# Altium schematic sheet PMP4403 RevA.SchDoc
size 431 x 279 mm; Date: Not shown in title block; ApprovedBy: Not shown in title block; CheckedBy: Not shown in title block; Author: Not shown in title block; CompanyName: Not shown in title block; Engineer: Jackyzhang; Organization: Not shown in title block; Address1: Not shown in title block; Address2: Not shown in title block; Address3: Not shown in title block; Address4: Not shown in title block; DocumentNumber: 1; Revision: A; SheetNumber: 1; SheetTotal: 1; PageSetup: Record=PageOptions¦CenterHorizontal=True¦CenterVertical=True¦PrintScale=1.00¦XCorrection=1.00¦YCorrection=1.00¦PrintKind=0¦BorderSize=5000000¦LeftOffset=0¦BottomOffset=0¦Orientation=2¦PaperLength=1000¦PaperWidth=1000¦Scale=100¦PaperSource=15¦PrintQuality=600¦MediaType=1¦DitherType=10¦PaperKind=Letter¦PrintScaleMode=1
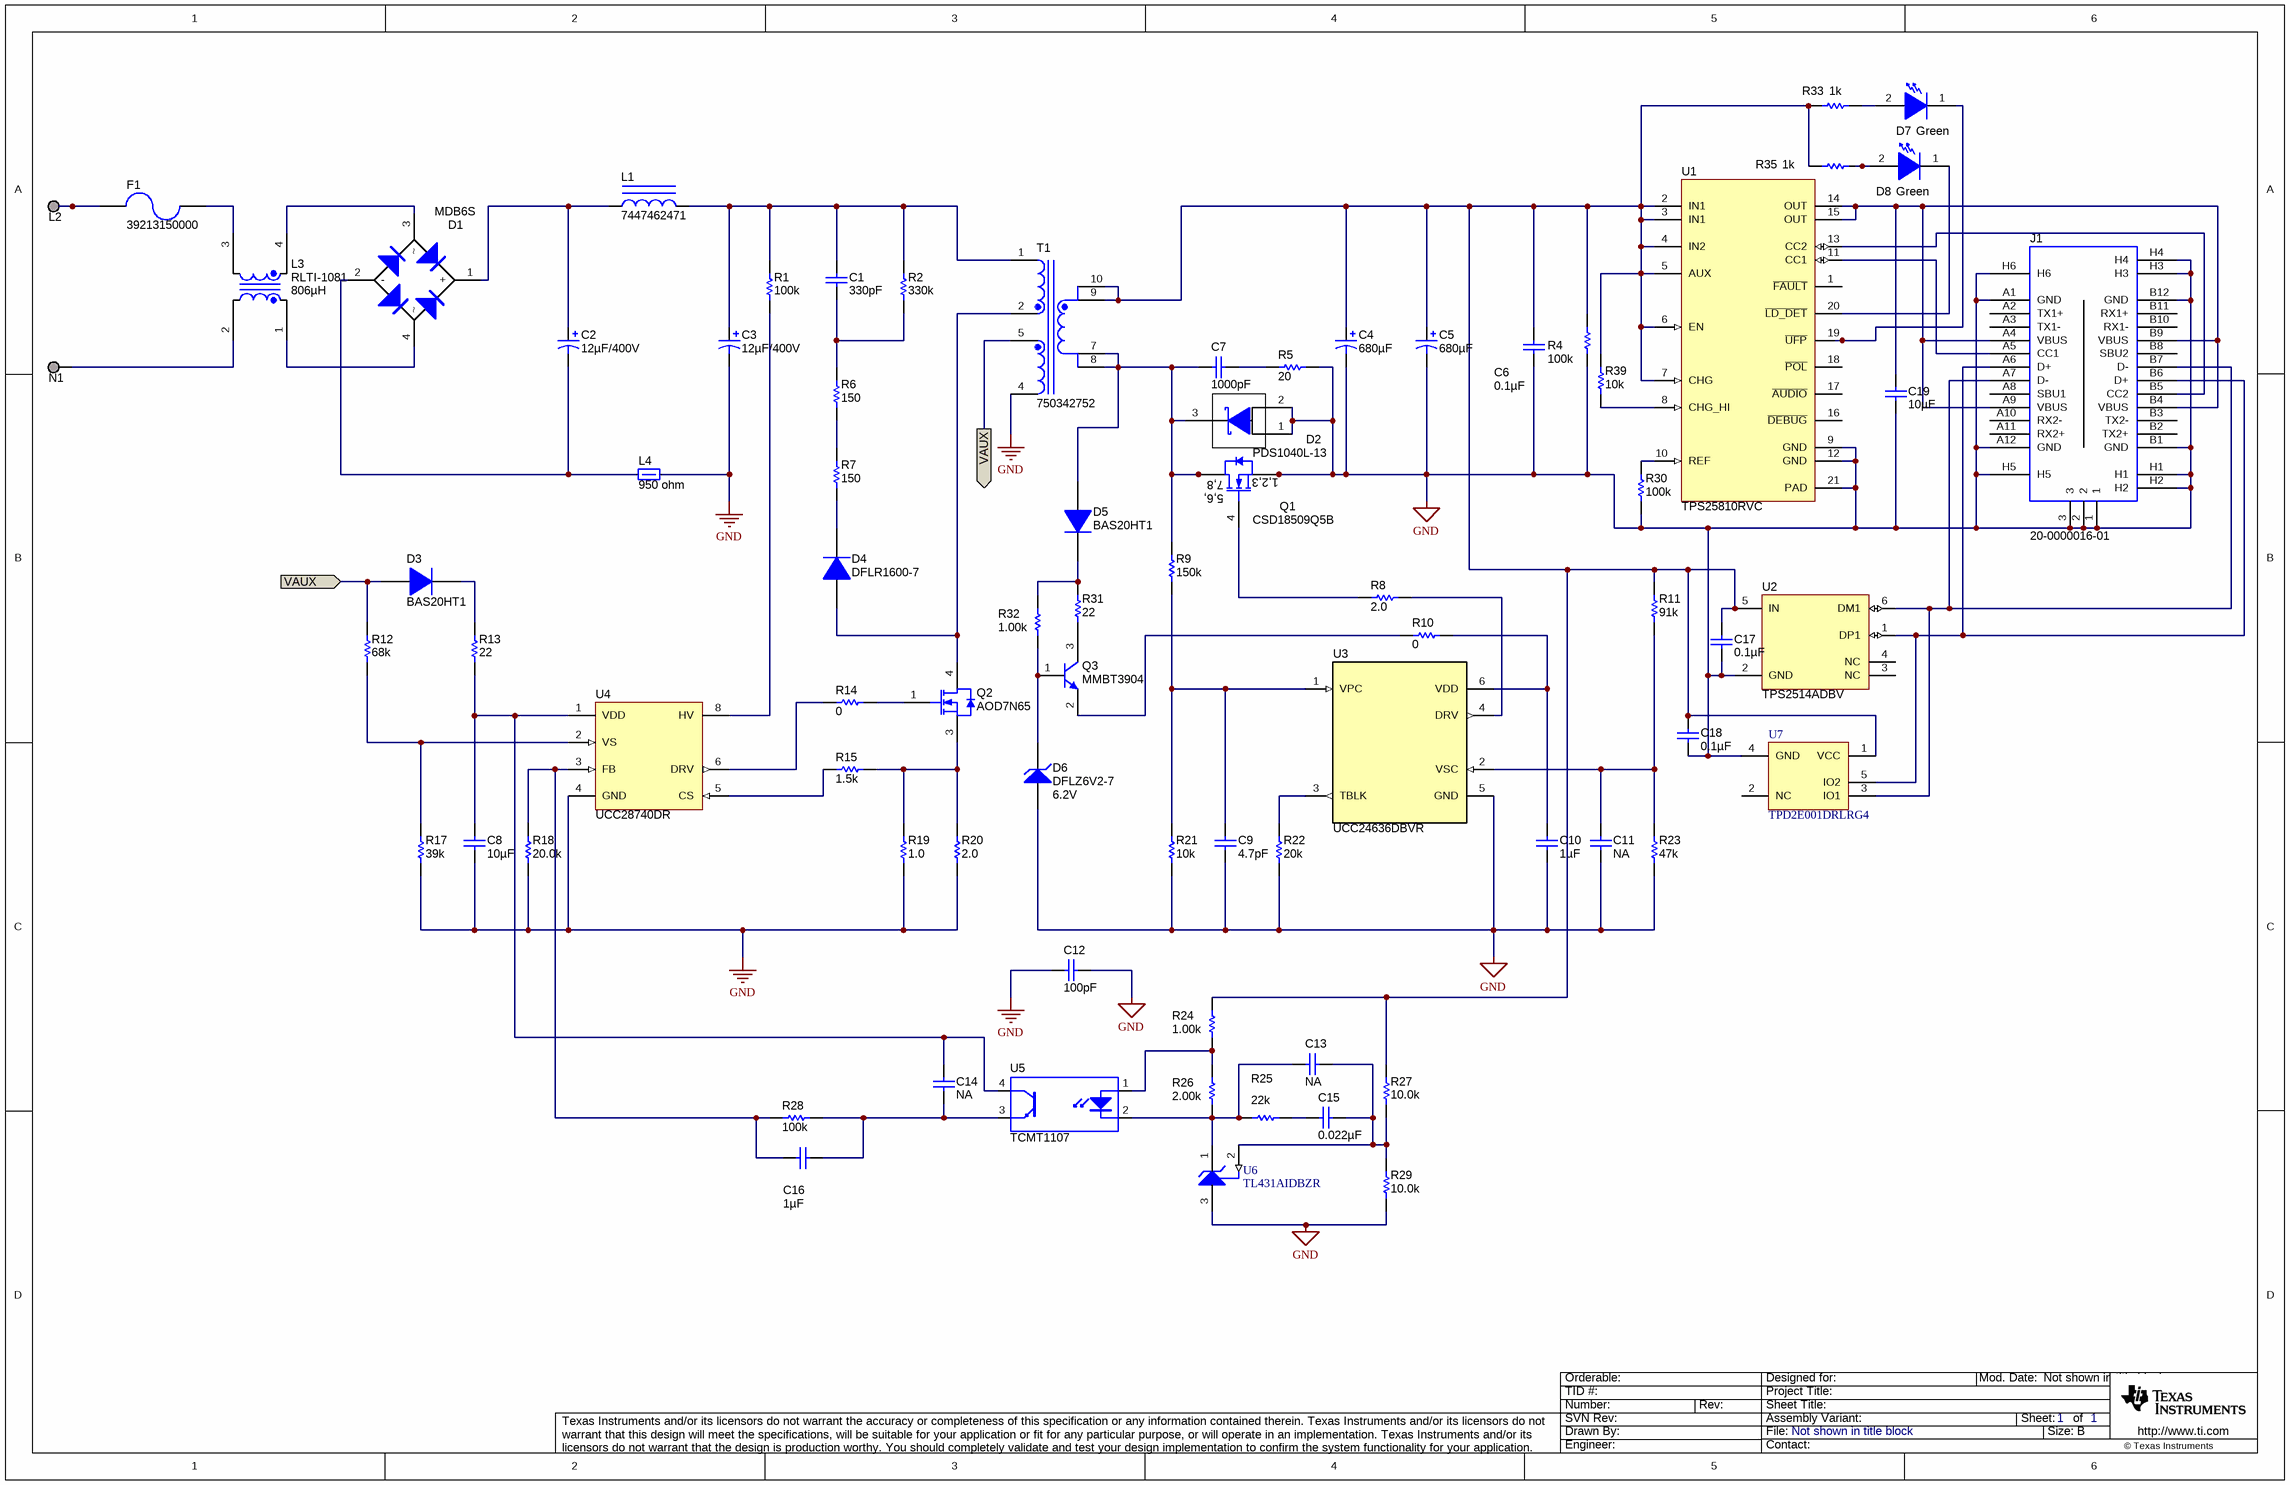
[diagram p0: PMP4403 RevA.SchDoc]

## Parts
C1  ValueDisplayed: 330pF  [1206]  (hidden comment: GRM31A5C2J331JW01D)
C2  ValueDisplayed: 12µF/400V  [CAPPR5-10X20]  (hidden comment: EEUED2G100)
C3  ValueDisplayed: 12µF/400V  [CAPPR5-10X20]  (hidden comment: EEUED2G100)
C4  ValueDisplayed: 680µF  [SEPC_C9]  (hidden comment: 6SEPC470MW)
C5  ValueDisplayed: 680µF  [SEPC_C9]  (hidden comment: 6SEPC470MW)
C6  ValueDisplayed: 0.1µF  [0603]  (hidden comment: C1608X7R1E104K)
C7  ValueDisplayed: 1000pF  [0603]  (hidden comment: 06035A102KAT2A)
C8  ValueDisplayed: 10µF  [1206_190]  (hidden comment: GMK316AB7106KL-TR)
C9  ValueDisplayed: 4.7pF  [0603]  (hidden comment: 06035A150JAT2A)
C10  ValueDisplayed: 1µF  [0603]  (hidden comment: GRM188R61E105KA12D)
C11  ValueDisplayed: NA  [0603]  (hidden comment: 06035A150JAT2A)
C12  ValueDisplayed: 100pF  [CAPRD1000W60D1000H1400]  (hidden comment: DE1B3KX101K)
C13  ValueDisplayed: NA  [0603]  (hidden comment: C0603X223K5RACTU)
C14  ValueDisplayed: NA  [0603]  (hidden comment: C0603X223K5RACTU)
C15  ValueDisplayed: 0.022µF  [0603]  (hidden comment: C0603X223K5RACTU)
C16  ValueDisplayed: 1µF  [0603_095]  (hidden comment: C0603C105K3RACTU)
C17  ValueDisplayed: 0.1µF  [0603]  (hidden comment: 06033C104JAT2A)
C18  ValueDisplayed: 0.1µF  [0603]  (hidden comment: 06033C104JAT2A)
C19  ValueDisplayed: 10µF  [0805_HV]  (hidden comment: C0805C106K8PACTU)
D1  MDB6S  [MICRODIP_4]
D2  PDS1040L-13  [PowerDI5]
D3  BAS20HT1  [sod-323]
D4  DFLR1600-7  [powerDI123]
D5  BAS20HT1  [sod-323]
D6  DFLZ6V2-7  value 6.2V  [powerDI123]
D7  value Green  [WL-SMCW_GREEN]  (hidden comment: 150060GS75000)
D8  value Green  [WL-SMCW_GREEN]  (hidden comment: 150060GS75000)
F1  39213150000  [FUSE_392]
J1  20-0000016-01  [Lintes_20-0000016-01]
L1  7447462471  [WE-TI_5075]
L2  TESTPOINT  [Keystone_5019]  (value not drawn)  (no BOM)
L3  RLTI-1081  ValueDisplayed: 806µH  [IND_RLTI-1081]
L4  value 950 ohm  [1206]  (hidden comment: HZ1206E152R-10)
N1  TESTPOINT  [Keystone_5019]  (value not drawn)  (no BOM)
Q1  CSD18509Q5B  [TRANS_NexFET_Q5B]
Q2  AOD7N65  [DPAK]
Q3  MMBT3904  [SOT-23]
R1  ValueDisplayed: 100k  [1206]  (hidden comment: CRCW1206100KJNEA)
R2  ValueDisplayed: 330k  [1206]  (hidden comment: CRCW1206330KJNEA)
R4  ValueDisplayed: 100k  [0603]  (hidden comment: CRCW0603100KJNEA)
R5  ValueDisplayed: 20  [0805_HV]  (hidden comment: CRCW080520R0JNEA)
R6  ValueDisplayed: 150  [1206]  (hidden comment: CRCW1206150RJNEA)
R7  ValueDisplayed: 150  [1206]  (hidden comment: CRCW1206150RJNEA)
R8  ValueDisplayed: 2.0  [0603]  (hidden comment: CRCW06032R00JNEA)
R9  ValueDisplayed: 150k  [0603]  (hidden comment: CRCW0603150KFKEA)
R10  ValueDisplayed: 0  [0603]  (hidden comment: CRCW06032R00JNEA)
R11  ValueDisplayed: 91k  [0603]  (hidden comment: CRCW060391K0JNEA)
R12  ValueDisplayed: 68k  [0603]  (hidden comment: CRCW060368K0JNEA)
R13  ValueDisplayed: 22  [0603]  (hidden comment: CRCW060322R0JNEA)
R14  ValueDisplayed: 0  [0603]  (hidden comment: CRCW06030000Z0EA)
R15  ValueDisplayed: 1.5k  [0603]  (hidden comment: CRCW06031K50JNEA)
R17  ValueDisplayed: 39k  [0603]  (hidden comment: CRCW060339K0JNEA)
R18  ValueDisplayed: 20.0k  [0603]  (hidden comment: CRCW060320K0FKEA)
R19  ValueDisplayed: 1.0  [1206]  (hidden comment: CRCW12061R00JNEA)
R20  ValueDisplayed: 2.0  [1206]  (hidden comment: CRCW12062R00JNEA)
R21  ValueDisplayed: 10k  [0603]  (hidden comment: CRCW060310K0JNEA)
R22  ValueDisplayed: 20k  [0603]  (hidden comment: CRCW060313K0JNEA)
R23  ValueDisplayed: 47k  [0603]  (hidden comment: CRCW060347K0JNEA)
R24  ValueDisplayed: 1.00k  [0603]  (hidden comment: CRCW06031K00FKEA)
R25  ValueDisplayed: 22k  [0603]  (hidden comment: CRCW060322K0JNEA)
R26  ValueDisplayed: 2.00k  [0603]  (hidden comment: CRCW06032K00FKEA)
R27  ValueDisplayed: 10.0k  [0603]  (hidden comment: CRCW060310K0FKEA)
R28  ValueDisplayed: 100k  [0603]  (hidden comment: CRCW0603100KFKEA)
R29  ValueDisplayed: 10.0k  [0603]  (hidden comment: CRCW060310K0FKEA)
R30  ValueDisplayed: 100k  [0603]  (hidden comment: CRCW0603100KFKEA)
R31  ValueDisplayed: 22  [0805_HV]  (hidden comment: CRCW080522R0JNEA)
R32  ValueDisplayed: 1.00k  [0603]  (hidden comment: CRCW06031K00FKEA)
R33  ValueDisplayed: 1k  [0603]  (hidden comment: CRCW060310K0JNEA)
R35  ValueDisplayed: 1k  [0603]  (hidden comment: CRCW060310K0JNEA)
R39  ValueDisplayed: 10k  [0603]  (hidden comment: CRCW060310K0JNEA)
T1  750342752  [Wurth_750342752]
U1  TPS25810RVC  [RVC0020A]
U2  TPS2514ADBV  [DBV0006A_N]
U3  UCC24636DBVR  [DBV0006A_N]
U4  UCC28740DR  [D0007A_N]
U5  TCMT1107  [SOP-4]
U6  TL431AIDBZR  [DBZ0003A_N]
U7  TPD2E001DRLRG4  [DRL0005A]

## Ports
VAUX (in), VAUX (out)

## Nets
GND: C3.2(-) C4.2(-) C5.2(-) C6.2 C8.2 C9.2 C10.2 C11.2 C12.1 C12.2 C17.2 C18.2 C19.2 D2.1(A) D2.2(A) D6.2(A) J1.1 J1.2 J1.3 J1.A1(GND) J1.A12(GND) J1.B1(GND) J1.B12(GND) J1.H1 J1.H2 J1.H3 J1.H4 J1.H5 J1.H6 L4.2 Q1.1(S) Q1.2(S) Q1.3(S) R4.1 R5.2 R17.1 R18.1 R19.1 R20.1 R21.1 R22.1 R23.1 R29.1 R30.1 T1.4 U1.9(GND) U1.12(GND) U1.21(PAD) U2.2(GND) U3.5(GND) U4.4(GND) U6.3(ANODE) U7.4(GND)
VAUX: D3.2(A) R12.2 T1.5 ; port VAUX
NetC1_1: C1.1 C3.1(+) L1.2 R1.2 R2.2 T1.1
NetC1_2: C1.2 R2.1 R6.2
NetC2_1: C2.1(+) D1.1(+) L1.1
NetC2_2: C2.2(-) D1.2(-) L4.1
NetC4_1: C4.1(+) C5.1(+) C6.1 C17.1 C18.1 R4.2 R11.2 R24.2 R27.2 R33.2 R35.2 R39.2 T1.9 T1.10 U1.2(IN1) U1.3(IN1) U1.4(IN2) U1.5(AUX) U1.6(EN) U1.7(CHG) U2.5(IN) U7.1(VCC)
NetC7_1: C7.1 R5.1
NetC7_2: C7.2 D2.3(K) D5.2(A) Q1.5(D) Q1.6(D) Q1.7(D) Q1.8(D) R9.2 T1.7 T1.8
NetC8_1: C8.1 C14.1 R13.1 U4.1(VDD) U5.4(C)
NetC9_1: C9.1 R9.1 R21.2 U3.1(VPC)
NetC10_1: C10.1 R10.1 U3.6(VDD)
NetC11_1: C11.1 R11.1 R23.2 U3.2(VSC)
NetC13_1: C13.1 C15.1 R27.1 R29.2 U6.2(REF)
NetC13_2: C13.2 R25.1 R26.1 U5.2(K) U6.1(CATHODE)
NetC14_2: C14.2 C16.1 R28.2 U5.3(E)
NetC15_2: C15.2 R25.2
NetC16_2: C16.2 R18.2 R28.1 U4.3(FB)
NetC19_1: C19.1 J1.A4(VBUS) J1.A9(VBUS) J1.B4(VBUS) J1.B9(VBUS) U1.14(OUT) U1.15(OUT)
NetD1_3: D1.3 L3.4
NetD1_4: D1.4 L3.1
NetD3_1: D3.1(K) R13.2
NetD4_1: D4.1(K) R7.1
NetD4_2: D4.2(A) Q2.4(D) T1.2
NetD5_1: D5.1(K) R31.2 R32.2
NetD6_1: D6.1(K) Q3.1(B) R32.1
NetD7_1: D7.1(K) U1.19(~{UFP})
NetD7_2: D7.2(A) R33.1
NetD8_1: D8.1(K) U1.20(~{LD_DET})
NetD8_2: D8.2(A) R35.1
NetF1_1: F1.1 L3.3
NetF1_2: F1.2 L2.1
NetJ1_A5: J1.A5(CC1) U1.11(CC1)
NetJ1_A6: J1.A6(D+) J1.B6(D+) U2.1(DP1) U7.5(IO2)
NetJ1_A7: J1.A7(D-) J1.B7(D-) U2.6(DM1) U7.3(IO1)
NetJ1_B5: J1.B5(CC2) U1.13(CC2)
NetL3_2: L3.2 N1.1
NetQ1_4: Q1.4(G) R8.1
NetQ2_1: Q2.1(G) R14.2
NetQ2_3: Q2.3(S) R15.2 R19.2 R20.2
NetQ3_2: Q3.2(E) R10.2
NetQ3_3: Q3.3(C) R31.1
NetR1_1: R1.1 U4.8(HV)
NetR6_1: R6.1 R7.2
NetR8_2: R8.2 U3.4(DRV)
NetR12_1: R12.1 R17.2 U4.2(VS)
NetR14_1: R14.1 U4.6(DRV)
NetR15_1: R15.1 U4.5(CS)
NetR22_2: R22.2 U3.3(TBLK)
NetR24_1: R24.1 R26.2 U5.1(A)
NetR30_2: R30.2 U1.10(REF)
NetR39_1: R39.1 U1.8(CHG_HI)

Not connected (* = marked no-connect by the designer): J1 A2(TX1+) A3(TX1-) A8(SBU1) A10(RX2-) A11(RX2+) B2(TX2+) B3(TX2-) B8(SBU2) B10(RX1-) B11(RX1+); U1 1(~{FAULT}) 16(~{DEBUG}) 17(~{AUDIO}) 18(~{POL}); U2 3(NC) 4(NC); U7 2(NC)

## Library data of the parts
C1 = GRM31A5C2J331JW01D: CAP, CERM, 330 pF, 630 V, +/- 5%, C0G/NP0, 1206; Manufacturer: MuRata; Polarized: N; CompType: Capacitor; Value: 330pF; U/M: EA; Cap_F: 0.00000000033; Tolerance_%: 5; Value1: Unknown; VDC_V: 630; Value2: 630V; TaMin_C: -55; TaMax_C: 125
C2 C3 = EEUED2G100: CAP, AL, 10 µF, 400 V, +/- 20%, 2.864788 ohm, TH; Manufacturer: Panasonic; Polarized: Y; CompType: Capacitor; Value: 12uF; U/M: EA; Cap_F: 0.00001; Tolerance_%: 20; VDC_V: 400; Value2: 400V; IRMS_A: 0.3; TaMin_C: -25; TaMax_C: 105
C4 C5 = 6SEPC470MW: CAP, AL, 470 µF, 6.3 V, +/- 20%, 0.007 ohm, TH; Manufacturer: Panasonic; Polarized: Y; CompType: Capacitor; Value: 470uF; U/M: EA; Cap_F: 0.00047; Tolerance_%: 20; VDC_V: 6.3; Value2: 6.3V; ESR_ohm: 0.007; IRMS_A: 5.6; TaMin_C: -55; TaMax_C: 105; Cap_Case: 6.3x9
C6 = C1608X7R1E104K: CAP, CERM, 0.1 µF, 25 V, +/- 10%, X7R, 0603; Manufacturer: TDK; Polarized: N; CompType: Capacitor; Value: 0.1uF; U/M: EA; Cap_F: 0.0000001; Tolerance_%: 10; ESR_ohm: 0.017; Value1: 0.017 ohm; VDC_V: 25; Value2: 25V; TaMin_C: -55; TaMax_C: 125
C7 = 06035A102KAT2A: CAP, CERM, 1000 pF, 50 V, +/- 10%, C0G/NP0, 0603; Manufacturer: AVX; Polarized: N; CompType: Capacitor; Value: 1000pF; U/M: EA; Cap_F: 0.000000001; Tolerance_%: 10; ESR_ohm: 0.048; Value1: 0.048 ohm; VDC_V: 50; Value2: 50V; TaMin_C: -55; TaMax_C: 125
C8 = GMK316AB7106KL-TR: CAP, CERM, 10 µF, 35 V, +/- 10%, X7R, 1206_190; Manufacturer: Taiyo Yuden; Polarized: N; CompType: Capacitor; Value: 10uF; U/M: EA; Cap_F: 0.00001; Tolerance_%: 10; Value1: Unknown; VDC_V: 35; Value2: 35V; TaMin_C: -55; TaMax_C: 125; Cap_Case: 1206
C9 C11 = 06035A150JAT2A: CAP, CERM, 15 pF, 50 V, +/- 5%, C0G/NP0, 0603; Manufacturer: AVX; Polarized: N; CompType: Capacitor; Value: 15pF; U/M: EA; Cap_F: 0.000000000015; Tolerance_%: 5; ESR_ohm: 0.32; Value1: 0.32 ohm; VDC_V: 50; Value2: 50V; TaMin_C: -55; TaMax_C: 125
C10 = GRM188R61E105KA12D: CAP, CERM, 1 µF, 25 V, +/- 10%, X5R, 0603; Manufacturer: MuRata; Polarized: N; CompType: Capacitor; Value: 1uF; U/M: EA; Cap_F: 0.000001; Tolerance_%: 10; Value1: Unknown; VDC_V: 25; Value2: 25V; TaMin_C: -55; TaMax_C: 85
C12 = DE1E3KX222MA5BA01: CAP, CERM, 100 pF, 250 V, +/- 20%, E, Disc 10x8mm; Manufacturer: MuRata; Polarized: N; CompType: Capacitor; Value: 100pF; U/M: EA; Cap_F: 0.0000000022; Tolerance_%: 20; Value1: Unknown; VDC_V: 250; Value2: 250V; TaMin_C: -25; TaMax_C: 85
C13-C15 = C0603X223K5RACTU: CAP, CERM, 0.022 µF, 50 V, +/- 10%, X7R, 0603; Manufacturer: Kemet; Polarized: N; CompType: Capacitor; Value: 0.022uF; U/M: EA; Cap_F: 0.000000022; Tolerance_%: 10; Value1: Unknown; VDC_V: 50; Value2: 50V; TaMin_C: -55; TaMax_C: 125
C16 = C0603C105K3RACTU: CAP, CERM, 1 µF, 25 V, +/- 10%, X7R, 0603_095; Manufacturer: Kemet; Polarized: N; CompType: Capacitor; Value: 1uF; U/M: EA; Cap_F: 0.000001; Tolerance_%: 10; Value1: Unknown; VDC_V: 25; Value2: 25V; TaMin_C: -55; TaMax_C: 125; Cap_Case: 0603
C17 C18 = 06033C104JAT2A: CAP, CERM, 0.1 µF, 25 V, +/- 5%, X7R, 0603; Manufacturer: AVX; Polarized: N; CompType: Capacitor; Value: 0.1uF; U/M: EA; Cap_F: 0.0000001; Tolerance_%: 5; ESR_ohm: 0.05; Value1: 0.05 ohm; VDC_V: 25; Value2: 25V; TaMin_C: -55; TaMax_C: 125
C19 = C0805C106K8PACTU: CAP, CERM, 10 µF, 10 V, +/- 10%, X5R, 0805; Manufacturer: Kemet; Polarized: N; CompType: Capacitor; Value: 10uF; U/M: EA; Cap_F: 0.00001; Tolerance_%: 10; ESR_ohm: 0.003; Value1: 0.003 ohm; Value2: 10V; IRMS_A: 11.43; TaMin_C: -55; TaMax_C: 85; Cap_Case: 0805
D1 = MDB6S: Diode, Switching-Bridge, 600 V, 1 A, Diode Bridge,6.5x1.3x5.0mm, SMT; Manufacturer: Fairchild Semiconductor; U/M: EA; Vf_V: 1.1; Value: 600V; Value1: 1A; Value2: 1.1V; Io_A: 1; Vr_V: 600; TJmax_C: 150
D2 = PDS1040L-13: Diode, Schottky, 40 V, 10 A, PowerDI5; Manufacturer: Diodes Inc.; U/M: EA; Vf_V: 0.49; Value: 40V; Value1: 10A; Value2: 0.49V; Io_A: 10; Vr_V: 40; TJmax_C: 150; RJC_CperW: 85
D3 D5 = BAV20WS-TP: Diode, P-N, 150 V, 0.2 A, SOD-323; Manufacturer: ON Semiconductor; U/M: EA; Vf_V: 1.25; Value: 150V; Value1: 0.2A; Value2: 1.25V; Io_A: 0.2; Vr_V: 150
D4 = DFLR1600-7: Diode, Standard Recovery Rectifier, 600 V, 1 A, PowerDI123; Manufacturer: Diodes Inc.; U/M: EA; Vf_V: 1.1; Value: 600V; Value1: 1A; Value2: 1.1V; Io_A: 1; Vr_V: 600; TJmax_C: 150
D6 = DFLZ6V2-7: Diode, Zener, 6.2 V, 1 W, PowerDI123; Manufacturer: Diodes Inc.; SymbolCreator: a0412235; U/M: EA; Power_W: 1; Vz_V: 6.2; Value1: 1W; RJA_CperW: 110
D7 D8 = 150060GS75000: LED, Green, SMD; Manufacturer: Wurth Elektronik; Type: InGaN; Vf_V: 3.2; Value2: 3.2V; Io_A: 0.02; Tjmax_C: 85; Value1: W; Angle: 140; U/M: EA
F1 = 39213150000: Fuse, 3.15 A, 250 V, TH; Manufacturer: Littelfuse; U/M: EA; OpeningTime_200%_max: 120; VDC_V: 250; Irating_A: 3.15; Vdrop: 0.08; Soldering_Wave_MaxTemp_C: 260; Soldering_Wave_MaxTime_s: 5
J1 = 20-0000016-01: Connector, Receptacle, USB Type C, R/A, SMT; Manufacturer: Lintes Technology; SymbolCreator: Altium; U/M: EA
L1 = 7447462471: Inductor, Unshielded Drum Core, Ferrite, 470 µH, 0.35 A, 1.58 ohm, TH; Manufacturer: Wurth Elektronik; Value: 470uH; Ind_H: 470.0E-6; ValueDisplayed: 470µH; Imax_A: 0.35; Irms: 0.35A @ 40C rise; Isat: 0.4A @ 10% inductance drop; DCR_ohm: 1.58; Value2: 0.35A
L2 N1 = 5019: Test Point, Miniature, SMT; Manufacturer: Keystone; CompType: Test Point Loop; U/M: EA
L3 = RLTI-1081: Coupled inductor, 806 µH,  A, 0.27 ohm, +/- 25%, TH; Manufacturer: Renco Electronics; SymbolCreator: a0412235; Ind_H: 806.0E-6; DCR_ohm: 0.27; Tolerance_%: 25; Value: 806uH
L4 = HZ1206E152R-10: Ferrite Bead, 950 ohm @ 100 MHz, 0.5 A, 1206; Manufacturer: Laird-Signal Integrity Products; Imax_A: 0.5; DCR_ohm: 0.3; Value1: 0.3 ohm; Value2: 0.5A; ZTyp@100MHz_Ohm: 950; Ztyp@1GHz_Ohm: 57
Q1 = CSD18509Q5B: MOSFET, N-CH, 40 V, 38 A, SON 5x6mm; Manufacturer: Texas Instruments; Alternate Manufacturer: None; U/M: EA; ChType: N; Value: 40V; VdsMax_V: 40; Value1: 0.0017 ohm; Rdson45_ohm: 0.0017; Value2: 150 nC; QgTyp_nC: 150; Vgs_V: 20; IdsMax_A: 38
Q2 = AOD7N65: MOSFET, N-CH, 650 V, 7 A, DPAK; Manufacturer: AOS; Alternate Manufacturer: None; U/M: EA; ChType: N; Value: 650V; VdsMax_V: 650; Value1: ? ohm; Value2: 19.6 nC; QgTyp_nC: 19.6; Vgs_V: 30; IdsMax_A: 7
Q3 = MMBT3904, Fairchild Semiconductor: Transistor, NPN, 40 V, 0.2 A, SOT-23; CompType: BJT; PNP: 0; NPN: 1; Vceo_V: 40; Vcesat1_V: 0.2; Value: 40 V; Value1: 0.2 A; HfeMax: 300; TaMin_C: -55; TaMax_C: 150; U/M: EA
R1 = CRCW1206100KJNEA: RES, 100 k, 5%, 0.25 W, 1206; Manufacturer: Vishay-Dale; CompType: Resistor; Value: 100k; Res_ohm: 100000; Tolerance_%: 5; Power_W: 0.25; Value2: 0.25W; VDC_V: 200; TempCo: 200 ppm/C; EIA_Code: E24; U/M: EA
R2 = CRCW1206330KJNEA: RES, 330 k, 5%, 0.25 W, 1206; Manufacturer: Vishay-Dale; CompType: Resistor; Value: 330k; Res_ohm: 330000; Tolerance_%: 5; Power_W: 0.25; Value2: 0.25W; VDC_V: 200; TempCo: 200 ppm/C; EIA_Code: E24; U/M: EA
R4 = CRCW0603100KJNEA: RES, 100 k, 5%, 0.1 W, 0603; Manufacturer: Vishay-Dale; CompType: Resistor; Value: 100k; Res_ohm: 100000; Tolerance_%: 5; Power_W: 0.1; Value2: 0.1W; VDC_V: 75; TempCo: 200 ppm/C; EIA_Code: E24; U/M: EA
R5 = CRCW080520R0JNEA: RES, 20, 5%, 0.125 W, 0805; Manufacturer: Vishay-Dale; CompType: Resistor; Value: 20; Value_Code: 20R0; Tolerance_%: 5; Power_W: 0.125; Value2: 0.125W; VDC_V: 150; TempCo: 200 ppm/C; EIA_Code: E24; U/M: EA
R6 R7 = CRCW1206150RJNEA: RES, 150, 5%, 0.25 W, 1206; Manufacturer: Vishay-Dale; CompType: Resistor; Value: 150; Value_Code: 150R; Tolerance_%: 5; Power_W: 0.25; Value2: 0.25W; VDC_V: 200; TempCo: 200 ppm/C; EIA_Code: E24; U/M: EA
R8 R10 = CRCW06032R00JNEA: RES, 2.0, 5%, 0.1 W, 0603; Manufacturer: Vishay-Dale; CompType: Resistor; Value: 2.0; Res_ohm: 2; Value_Code: 2R00; Tolerance_%: 5; Power_W: 0.1; Value2: 0.1W; VDC_V: 75; TempCo: 200 ppm/C; EIA_Code: E24; U/M: EA
R9 = CRCW0603150KFKEA: RES, 150 k, 1%, 0.1 W, 0603; Manufacturer: Vishay-Dale; CompType: Resistor; Value: 150k; Res_ohm: 150000; Tolerance_%: 1; Power_W: 0.1; Value2: 0.1W; VDC_V: 75; TempCo: 100 ppm/C; EIA_Code: E96; U/M: EA
R11 = CRCW060391K0JNEA: RES, 91 k, 5%, 0.1 W, 0603; Manufacturer: Vishay-Dale; CompType: Resistor; Value: 91k; Res_ohm: 91000; Value_Code: 91k0; Tolerance_%: 5; Power_W: 0.1; Value2: 0.1W; VDC_V: 75; TempCo: 200 ppm/C; EIA_Code: E24; U/M: EA
R12 = CRCW060368K0JNEA: RES, 68 k, 5%, 0.1 W, 0603; Manufacturer: Vishay-Dale; CompType: Resistor; Value: 68k; Res_ohm: 68000; Value_Code: 68k0; Tolerance_%: 5; Power_W: 0.1; Value2: 0.1W; VDC_V: 75; TempCo: 200 ppm/C; EIA_Code: E24; U/M: EA
R13 = CRCW060322R0JNEA: RES, 22, 5%, 0.1 W, 0603; Manufacturer: Vishay-Dale; CompType: Resistor; Value: 22; Value_Code: 22R0; Tolerance_%: 5; Power_W: 0.1; Value2: 0.1W; VDC_V: 75; TempCo: 200 ppm/C; EIA_Code: E24; U/M: EA
R14 = CRCW06030000Z0EA: RES, 0, 5%, 0.1 W, 0603; Manufacturer: Vishay-Dale; CompType: Resistor; Value: 0; Value_Code: 0000; Tolerance_%: 5; Power_W: 0.1; Value2: 0.1W; VDC_V: 75; TempCo: 200 ppm/C; EIA_Code: E24; U/M: EA
R15 = CRCW06031K50JNEA: RES, 1.5 k, 5%, 0.1 W, 0603; Manufacturer: Vishay-Dale; CompType: Resistor; Value: 1.5k; Res_ohm: 1500; Value_Code: 1k50; Tolerance_%: 5; Power_W: 0.1; Value2: 0.1W; VDC_V: 75; TempCo: 200 ppm/C; EIA_Code: E24; U/M: EA
R17 = CRCW060339K0JNEA: RES, 39 k, 5%, 0.1 W, 0603; Manufacturer: Vishay-Dale; CompType: Resistor; Value: 39k; Res_ohm: 39000; Value_Code: 39k0; Tolerance_%: 5; Power_W: 0.1; Value2: 0.1W; VDC_V: 75; TempCo: 200 ppm/C; EIA_Code: E24; U/M: EA
R18 = CRCW060320K0FKEA: RES, 20.0 k, 1%, 0.1 W, 0603; Manufacturer: Vishay-Dale; CompType: Resistor; Value: 20.0k; Res_ohm: 20000; Value_Code: 20k0; Tolerance_%: 1; Power_W: 0.1; Value2: 0.1W; VDC_V: 75; TempCo: 100 ppm/C; EIA_Code: E96; U/M: EA
R19 = CRCW12061R00JNEA: RES, 1.0, 5%, 0.25 W, 1206; Manufacturer: Vishay-Dale; CompType: Resistor; Value: 1.0; Res_ohm: 1; Value_Code: 1R00; Tolerance_%: 5; Power_W: 0.25; Value2: 0.25W; VDC_V: 200; TempCo: 200 ppm/C; EIA_Code: E24; U/M: EA
R20 = CRCW12062R00JNEA: RES, 2.0, 5%, 0.25 W, 1206; Manufacturer: Vishay-Dale; CompType: Resistor; Value: 2.0; Res_ohm: 2; Value_Code: 2R00; Tolerance_%: 5; Power_W: 0.25; Value2: 0.25W; VDC_V: 200; TempCo: 200 ppm/C; EIA_Code: E24; U/M: EA
R21 R33 R35 R39 = CRCW060310K0JNEA: RES, 10 k, 5%, 0.1 W, 0603; Manufacturer: Vishay-Dale; CompType: Resistor; Value: 10k; Res_ohm: 10000; Value_Code: 10k0; Tolerance_%: 5; Power_W: 0.1; Value2: 0.1W; VDC_V: 75; TempCo: 200 ppm/C; EIA_Code: E24; U/M: EA
R22 = CRCW060313K0JNEA: RES, 13 k, 5%, 0.1 W, 0603; Manufacturer: Vishay-Dale; CompType: Resistor; Value: 13k; Res_ohm: 13000; Value_Code: 13k0; Tolerance_%: 5; Power_W: 0.1; Value2: 0.1W; VDC_V: 75; TempCo: 200 ppm/C; EIA_Code: E24; U/M: EA
R23 = CRCW060347K0JNEA: RES, 47 k, 5%, 0.1 W, 0603; Manufacturer: Vishay-Dale; CompType: Resistor; Value: 47k; Res_ohm: 47000; Value_Code: 47k0; Tolerance_%: 5; Power_W: 0.1; Value2: 0.1W; VDC_V: 75; TempCo: 200 ppm/C; EIA_Code: E24; U/M: EA
R24 R32 = CRCW06031K00FKEA: RES, 1.00 k, 1%, 0.1 W, 0603; Manufacturer: Vishay-Dale; CompType: Resistor; Value: 1.00k; Res_ohm: 1000; Value_Code: 1k00; Tolerance_%: 1; Power_W: 0.1; Value2: 0.1W; VDC_V: 75; TempCo: 100 ppm/C; EIA_Code: E96; U/M: EA
R25 = CRCW060322K0JNEA: RES, 22 k, 5%, 0.1 W, 0603; Manufacturer: Vishay-Dale; CompType: Resistor; Value: 22k; Res_ohm: 22000; Value_Code: 22k0; Tolerance_%: 5; Power_W: 0.1; Value2: 0.1W; VDC_V: 75; TempCo: 200 ppm/C; EIA_Code: E24; U/M: EA
R26 = CRCW06032K00FKEA: RES, 2.00 k, 1%, 0.1 W, 0603; Manufacturer: Vishay-Dale; CompType: Resistor; Value: 2.00k; Res_ohm: 2000; Value_Code: 2k00; Tolerance_%: 1; Power_W: 0.1; Value2: 0.1W; VDC_V: 75; TempCo: 100 ppm/C; EIA_Code: E96; U/M: EA
R27 R29 = CRCW060310K0FKEA: RES, 10.0 k, 1%, 0.1 W, 0603; Manufacturer: Vishay-Dale; CompType: Resistor; Value: 10.0k; Res_ohm: 10000; Value_Code: 10k0; Tolerance_%: 1; Power_W: 0.1; Value2: 0.1W; VDC_V: 75; TempCo: 100 ppm/C; EIA_Code: E96; U/M: EA
R28 R30 = CRCW0603100KFKEA: RES, 100 k, 1%, 0.1 W, 0603; Manufacturer: Vishay-Dale; CompType: Resistor; Value: 100k; Res_ohm: 100000; Tolerance_%: 1; Power_W: 0.1; Value2: 0.1W; VDC_V: 75; TempCo: 100 ppm/C; EIA_Code: E96; U/M: EA
R31 = CRCW080522R0JNEA: RES, 22, 5%, 0.125 W, 0805; Manufacturer: Vishay-Dale; CompType: Resistor; Value: 22; Value_Code: 22R0; Tolerance_%: 5; Power_W: 0.125; Value2: 0.125W; VDC_V: 150; TempCo: 200 ppm/C; EIA_Code: E24; U/M: EA
T1 = 750342752: Transformer, 515 uH, TH; Manufacturer: Wurth Elektronik; SymbolCreator: Altium; DCR_Ohm: 0.66; Value: 515 uH; LeakageL: 20 uH; U/M: EA
U1 = TPS25810RVC: USB Type-C DFP Controller and Power Switch with Load Detection, RVC0020A; Manufacturer: Texas Instruments; SymbolCreator: Altium; CompType: IC; U/M: EA
U2 = TPS2514ADBV: USB Dedicated Charging Port Controller, DBV0006A; Manufacturer: Texas Instruments; SymbolCreator: a0411947; CompType: IC; U/M: EA
U3 = UCC24636DBVR: SYNCRONOUS RECTIFIER CONTROLLER WITH LOW POWER STANDBY, DBV0006A; Alternate PartNumber: UCC24636DBVT; Manufacturer: Texas Instruments; SymbolCreator: a0411947; CompType: IC; U/M: EA
U4 = UCC28740DR: Constant-Voltage, Constant-Current Flyback Controller Using Opto-Coupler Feedback, D0007A; Manufacturer: Texas Instruments; SymbolCreator: a0412235; CompType: IC; U/M: EA
U5 = TCMT1107: Optocoupler, 3.75 kV, 80-160% CTR, SMD-4; Manufacturer: Vishay-Semiconductor; CTR_Min: 80% @ 5mA; CTR_Max: 160% @ 5mA; Voltage_Isolation_Vrms: 3750; tr_typ: 4us; tf_typ: 4.7us; U/M: EA
U6 = TL431AIDBZR: Adjustable Precision Shunt Regulator, 34 ppm / degC, 100 mA, -40 to 85 degC, 3-pin SOT-23 (DBZ), Green (RoHS & no Sb/Br); Manufacturer: Texas Instruments; Alternate Manufacturer: None; Alternate PartNumber: Equivalent; Initial Accuracy @ 25/deg C(%): 1; Iout/Iz(Max)(mA): 100; Min Iz for Regulation(uA): 600; Rating: Catalog; SubFamily: Shunt Voltage Reference; Temp Coeff(Max)(ppm/ degree C): 92; Temp Coeff(Typ)(ppm/ degree C): 34; VO Adj(Max)(V): 36; VO Adj(Min)(V): 2.495
U7 = TPD2E001DRLRG4: Low-Capacitance + / - 15 kV ESD-Protection Array for High-Speed Data Interfaces, 2 Channels, -40 to +85 degC, 5-pin SOT (DRL), Green (RoHS & no Sb/Br); Manufacturer: Texas Instruments; Alternate Manufacturer: None; Alternate PartNumber: Equivalent; Breakdown Voltage(Min)(V): 11; IEC 61000-4-2 Air-Gap(+/- kV): 15; IEC 61000-4-2 Contact(+/- kV): 8; IO Capacitance(Typ)(pF): 1.5; IO Leakage Current(nA): 1; SubFamily: ESD Solution; USB High Speed: TRUE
